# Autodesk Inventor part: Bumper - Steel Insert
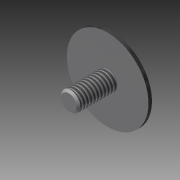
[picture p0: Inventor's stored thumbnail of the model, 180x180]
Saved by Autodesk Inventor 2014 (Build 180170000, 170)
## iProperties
Company: NHTSA/VRTC
Created: 2012-08
Material: Steel, Mild
Document SubType Name: Modeling
Designer: Mike Vanvoorhis
Density: 7.86 g/cm^3
Mass: 9.76632 g
Surface Area: 18.9612 cm^2
Volume: 1.24253 cm^3
Project: CHILD SIDE IMPACT SLED
Description: BUMPER sTEEL iNSERT
Appearance: Steel
Author: Dave Walker
Title: Bumper - Steel Insert
Subject: Child Side Impact Sled
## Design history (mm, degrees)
sketch "Sketch1"
  geometry: C1 r 16.675 at (0, 0); 1 further point
  constraints: 1 centre point, 1 coincident
  dimensions: "d0" = 33.3502 diameter of C1
extrude "Extrusion1" new body sketch "Sketch1" distance "d1" = 1.4224; taper "d2" = 0 deg
sketch "Sketch5"
  geometry: C1 r 16.675 at (0, 0) reference; C2 r 3.969 at (0, 0)
  constraints: 1 centre point, 1 coincident
  dimensions: "d28" = 7.9375 diameter of C2
extrude "Extrusion5" join sketch "Sketch5" distance "d31" = 15.875; taper "d32" = 0 deg
thread "Thread6" dims "d33" = 25.4, "d34" = 0
chamfer "Chamfer2" distance "d35" = 0.79375; stored, may be unused: second distance "d36" = 3.175, angle "d37" = 45 deg
body "Solid1"
